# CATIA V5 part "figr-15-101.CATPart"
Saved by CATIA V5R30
Part number: Part1
Bounding box of the stored display mesh (mm): x -52.43 to 60.529, y -25.631 to 32.893, z 0 to 4
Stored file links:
  D:\PROJECTS\CATIA V56R 2020\Resources\Parts File\c15_catia_v5_6r2020_prt\figr-15-101.CATPart
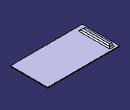
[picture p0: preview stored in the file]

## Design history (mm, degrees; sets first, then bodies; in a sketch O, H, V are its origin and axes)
SheetMetalParameters1: Thickness 1, BendRadius 5, KFactor 0.5 {= log(min(100,max(20*SheetMetalParameters1.BendRadius,SheetMetalParameters1.Thickness)/SheetMetalParameters1.Thickness))/log(100)/2}, ReliefRadialLength 1, ReliefAxialLength 2, MinimumBendRadius 0
Body1 (main body)
  Sketch1 on xy-plane, origin (0, 0, 0), H (1, 0, 0), V (0, 1, 0)
    line L1 (-52.4297, 32.8934) -> (60.5286, 32.8934)
    line L2 (60.5286, 32.8934) -> (60.5286, -25.6312)
    line L3 (60.5286, -25.6312) -> (-52.4297, -25.6312)
    line L4 (-52.4297, -25.6312) -> (-52.4297, 32.8934)
    horizontal: L1 H, L3 H
    vertical: L2 V, L4 V
  Wall1: Thickness 1, Profile Sketch1
  Sketch2 on face of Wall1, origin (0, 0, 1), H (1, 0, 0), V (0, 1, 0)
    line L1 (-47.3159, -16.5837) -> (-43.073, -16.5837)
    line L2 (-43.073, -16.5837) -> (-43.073, 26.788)
    line L3 (-43.073, 26.788) -> (-47.3159, 26.788)
    line L4 (-47.3159, 26.788) -> (-47.3159, -16.5837)
    horizontal: L1 H, L3 H
    vertical: L2 V, L4 V
  d_Stamp1: Stamp_FilletRadius 2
